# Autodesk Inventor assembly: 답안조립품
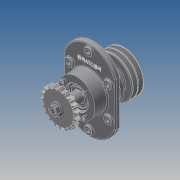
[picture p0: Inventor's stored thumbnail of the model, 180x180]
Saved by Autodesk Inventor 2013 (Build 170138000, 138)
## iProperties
Created: 2015-02
Part Number: 답안조립품
Document SubType Name: Assembly
Designer: kb543
Author: kb543
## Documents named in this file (12)
- C:\Users\kb543\Desktop\450207V1013\답안조립품.iam
- C:\Users\kb543\Desktop\450207V1013\1-본체.ipt
- C:\Users\kb543\Desktop\450207V1013\2-커버.ipt
- C:\Users\kb543\Desktop\450207V1013\3-축.ipt
- C:\Users\kb543\Desktop\450207V1013\4-V벨트풀리.ipt
- C:\Users\kb543\Desktop\450207V1013\5-체인 스프로킷.ipt
- C:\Users\kb543\Desktop\450207V1013\6-베어링 6206.ipt
- C:\Users\kb543\Desktop\450207V1013\7-부시.ipt
- C:\Users\kb543\Desktop\450207V1013\8-오일실 30x42.ipt
- C:\Users\kb543\Desktop\450207V1013\9-M16-너트.ipt
- C:\Users\kb543\Desktop\450207V1013\10-M6.ipt
- C:\Users\kb543\Desktop\450207V1013\11-키 6x6.ipt
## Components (23 placed, 11 different names)
1. 1-본체:1
2. 2-커버:1
3. 3-축:1 — 플러쉬:1
4. 4-V벨트풀리:1
5. 5-체인 스프로킷:1 — 플러쉬:1
6. 6-베어링 6206:1
7. 7-부시:1
8. 8-8-오일실 30x42:1
9. 9-M16 너트:1
10. 11-키 6x6:1
11. 2-커버:2
12. 8-8-오일실 30x42:2
13. 6-베어링 6206:2
14. 11-키 6x6:2
15. 9-M16 너트:2
16. 10-M6:2
17. 10-M6:3
18. 10-M6:4
19. 10-M6:5
20. 10-M6:1
21. 10-M6:6
22. 10-M6:7
23. 10-M6:8
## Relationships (1: Flush 1)
- 플러쉬:1 [Flush]: 3-축:1 ↔ 5-체인 스프로킷:1
